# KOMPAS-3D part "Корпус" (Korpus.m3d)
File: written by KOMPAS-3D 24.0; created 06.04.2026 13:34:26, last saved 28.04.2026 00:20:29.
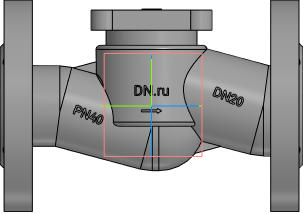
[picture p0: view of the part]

Document properties: Автор: R2D2; Полное имя файла: C:\Работа\ГОТОВЫЕ ИСХОДНИКИ\VSO2130M-F-S Клапан запорный сальниковый DN.ru Ду15-100 Ру40\исходные материалы\DN20\Korpus.m3d

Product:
- Body: Труба / Нестандартная труба / L = 90.6 мм  | qty 1
    Материал: Нестандартная труба (density 7856 kg/m3)
    Масса: 3.884845
    Раздел спецификации: Детали
    Примечание: 1,13 кг
    additional columns: Pipeline; 0.045; 0; 0; 0.002; 0.09061; true; 0.04
- Body: Труба / Нестандартная труба / L = 81.3 мм  | qty 1
    Материал: Нестандартная труба (density 7856 kg/m3)
    Масса: 3.884845
    Раздел спецификации: Детали
    Примечание: 0,8 кг
    additional columns: Pipeline; 0.04; 0; 0; 0.002; 0.08126; true; 0.04
- Body: Тело 4  | qty 1
    Материал: Нестандартная труба (density 7856 kg/m3)
    Масса: 3.884845
- Body: Тело 5  | qty 1
    Материал: Нестандартная труба (density 7856 kg/m3)
    Масса: 3.884845
- Body: Тело 8  | qty 1
    Материал: Нестандартная труба (density 7856 kg/m3)
    Масса: 3.884845
- Body: Тело 10  | qty 1
    Материал: Нестандартная труба (density 7856 kg/m3)
    Масса: 3.884845
- Body: Тело 11  | qty 1
    Материал: Нестандартная труба (density 7856 kg/m3)
    Масса: 3.884845
- Body: Тело 12  | qty 1
    Материал: Нестандартная труба (density 7856 kg/m3)
    Масса: 3.884845
- Body: Тело 13  | qty 1
    Материал: Нестандартная труба (density 7856 kg/m3)
    Масса: 3.884845
- Part/product: Корпус
    Масса: 6.9

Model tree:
1. Труба:1  (labels: {F703FF30-5BE6-4673-A7F1-8EDA1BE1E2D1}; SHAPEOBJECT3D_ATTR_BUTT; SHAPEOBJECT3D_ATTR_VALID; SHAPEOBJECT3D_ATTR_BUTT_AREA)
     PIPE_R = 3
2. Труба:2  (labels: {F703FF30-5BE6-4673-A7F1-8EDA1BE1E2D1}; SHAPEOBJECT3D_ATTR_BUTT; SHAPEOBJECT3D_ATTR_VALID; SHAPEOBJECT3D_ATTR_BUTT_AREA)
     PIPE_R = 3
3. Колонна
4. Элемент выдавливания:1
     Смещение 1 = -1; Смещение 2 = -5
5. Скругление:17  (with: Ребро.Элемент выдавливания:1)
     Радиус = 2
6. Скругление:18  (with: Ребро.Элемент выдавливания:1)
7. Скругление:24
     Радиус = 1.5
8. Элемент выдавливания:2
     Расстояние 1 = 6
9. Эскиз:4  (with: Грань.Элемент выдавливания:1)
10. Элемент выдавливания:3
     Расстояние 1 = 7.5
11. ОТЛИВКА
12. Скругление:6  (with: Грань.Элемент выдавливания:1)
     Радиус = 2
13. Элемент выдавливания:6  (with: Грань.Элемент выдавливания:1)
     Смещение 1 = 4
14. ЛЕЙБЛ
15. Элемент выдавливания:7  (with: Грань.Элемент выдавливания:1)
     Расстояние 1 = 28.4827; Смещение 1 = 1
16. Dn
17. Pn
18. Стрелочка
19. Элемент выдавливания:10  (with: Грань.Труба:1)
     Расстояние 1 = 23.3928; Смещение 1 = 1
20. Элемент выдавливания:11  (with: Грань.Труба:2)
     Расстояние 1 = 20.9914; Смещение 1 = 1
21. Элемент выдавливания:12  (with: Грань.Элемент выдавливания:1)
     Расстояние 1 = 28.4999; Смещение 1 = 1
22. Материал
23. Элемент выдавливания:13  (with: Грань.Элемент выдавливания:1)
     Расстояние 1 = 27.9952; Смещение 1 = 0.5
24. Фланец верх  (with: Грань.Элемент выдавливания:3)
25. Элемент выдавливания:14
     Расстояние 1 = 10
26. Эскиз:18  (with: Грань.Элемент выдавливания:14)
27. Элемент выдавливания:15
     Расстояние 1 = 0.5
28. Эскиз:19  (with: Грань.Элемент выдавливания:14, Ребро.Элемент выдавливания:14)
29. Элемент выдавливания:16  (with: Грань.Элемент выдавливания:14)
     Расстояние 1 = 0.5; Расстояние 2 = 11; Смещение 2 = 1
30. Фланец
31. Элемент вращения:1
     Угол 1 = 360
32. отвертие во фланце  (with: Грань.Элемент вращения:1)
33. Элемент выдавливания:8
34. Массив по концентрической сетке:2  (with: Элемент выдавливания:8, Эскиз:10, Грань.Элемент вращения:1)  (4 pattern instances)
     Шаг 2 = 360
35. Зеркальный массив:1
36. Экземпляр ( 1 )
37. Экземпляр ( 2 )  (with: Элемент вращения:1, Массив по концентрической сетке:2, Экземпляр ( 1 ), Элемент выдавливания:8)
38. Экземпляр ( 3 )  (with: Элемент выдавливания:8)
39. Экземпляр ( 4 )  (with: Элемент выдавливания:8)
40. Массив по концентрической сетке:3  (with: Элемент выдавливания:16, Эскиз:19)  (labels: Клапан запорный DN.ru Ду20 Ру40)  (4 pattern instances)
     Шаг 2 = 360

Expressions: DS/2+3; DN/2; LL/2; D1/2; D2/2-6
Referenced files in C:\Работа\ГОТОВЫЕ ИСХОДНИКИ\VSO2130M-F-S Клапан запорный сальниковый DN.ru Ду15-100 Ру40\исходные материалы\DN20\: VSO2130M-F-S Клапан запорный DN.ru Ду20 Ру40.a3d
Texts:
  GOST 26.020 Pr3
  var3D
  GS-C25
  смещение колонны вниз
  LL-10
  DN+20
  DS+10
  Труба / Нестандартная труба / L = %s мм
  Ось Y.Начало координат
